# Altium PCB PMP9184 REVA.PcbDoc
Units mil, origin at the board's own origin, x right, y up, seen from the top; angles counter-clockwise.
Board outline 2750 x 2500 mil, 2 copper layers (Top Layer, Bottom Layer), stack 64.8 mil thick; 44 components, 18 nets, 116 pads, 55 vias.
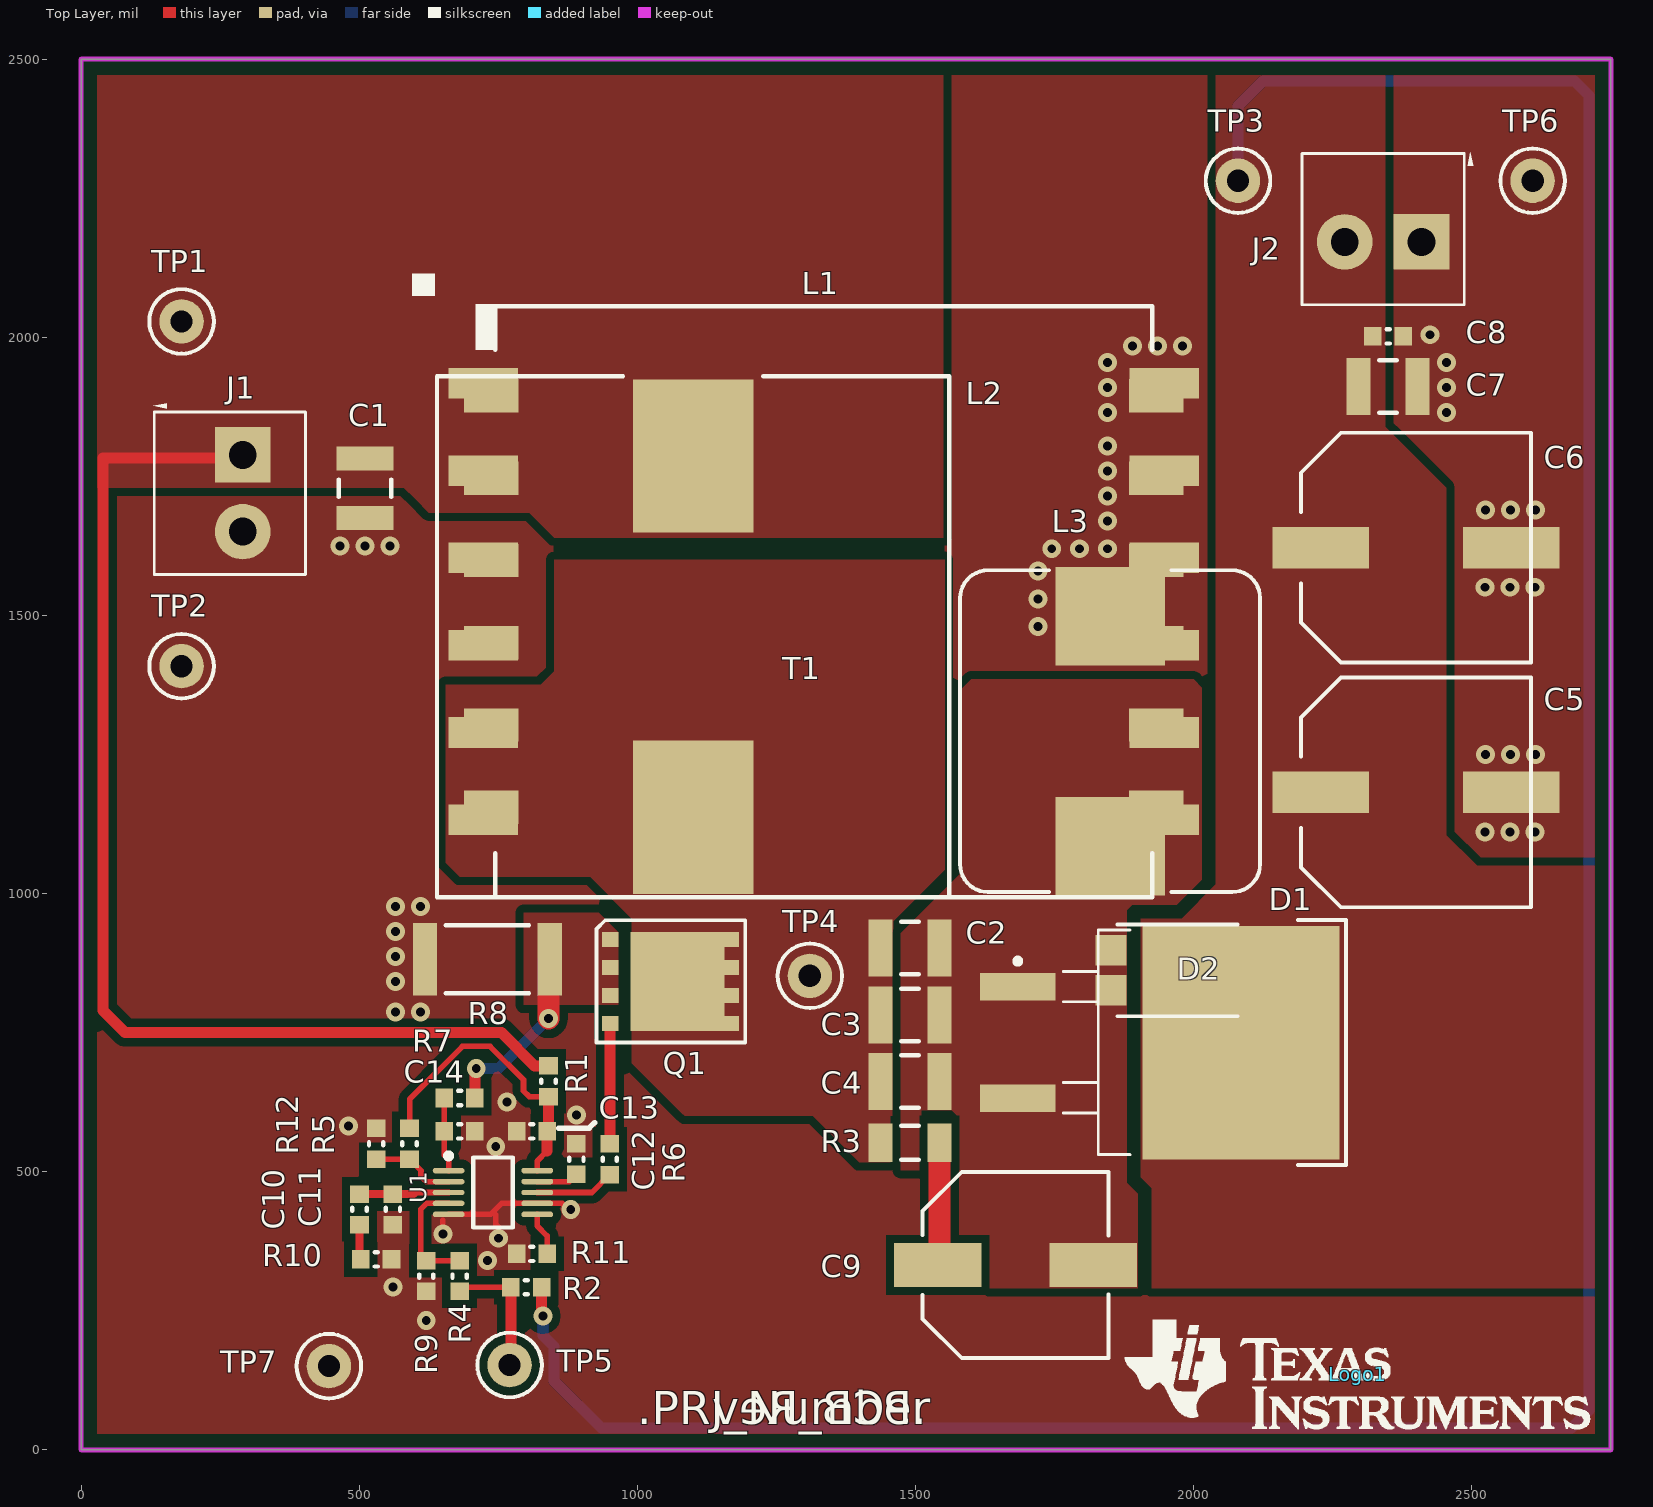
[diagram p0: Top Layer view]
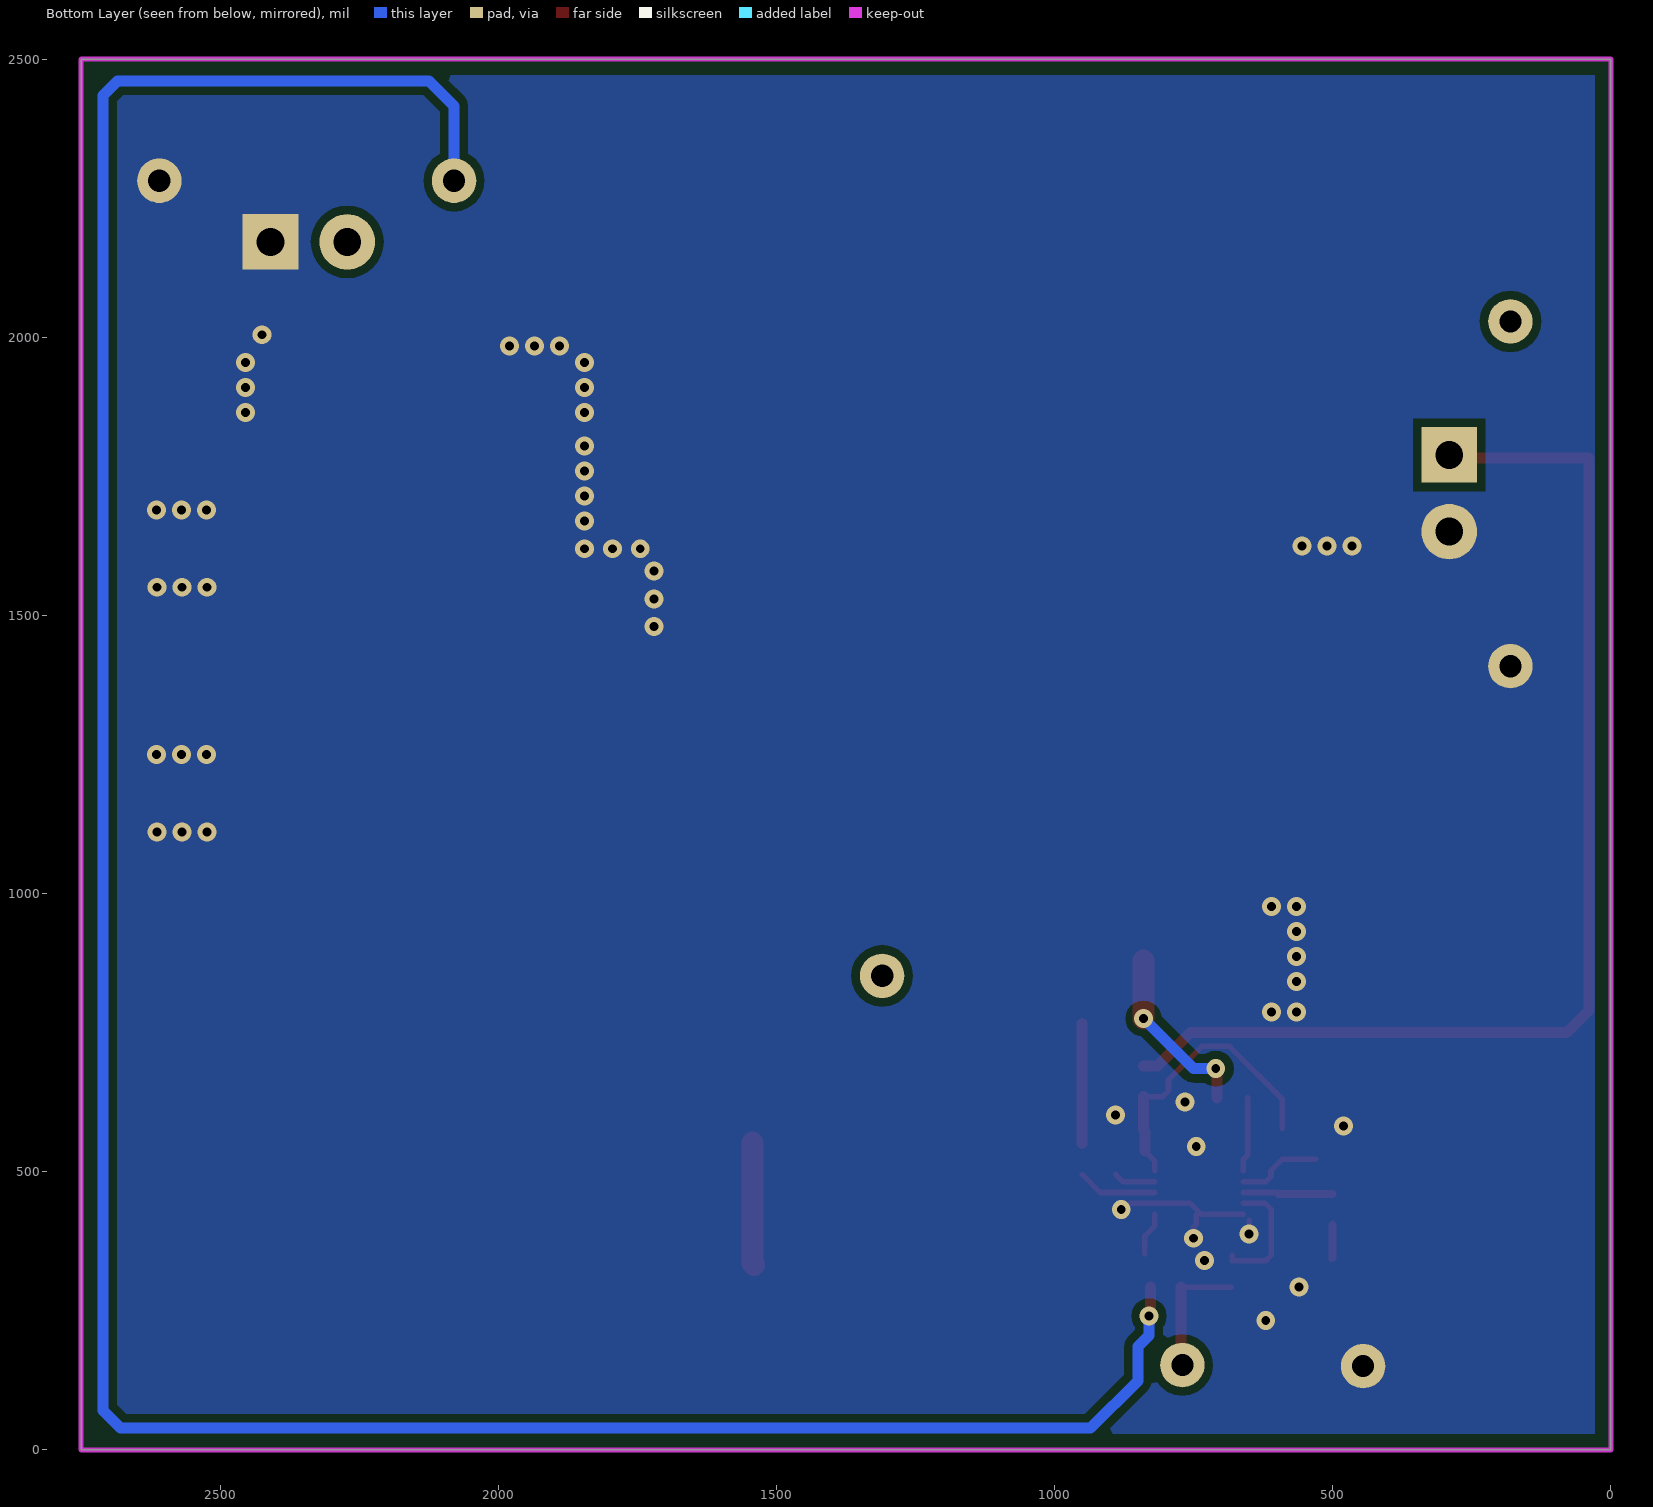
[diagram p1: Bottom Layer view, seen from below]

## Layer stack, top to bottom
Top Layer: signal copper 2.8
Dielectric: core 59.2, FR-4, Dk 4.8
Bottom Layer: signal copper 2.8

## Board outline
0,0 2750,0 2750,2500 0,2500

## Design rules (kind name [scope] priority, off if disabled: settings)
AcuteAngle [All] p1: minimum=4.50000000000000E+0001 checktracksonly=FALSE
AssemblyTestPointUsage [All] p1: valid=2
Clearance Clearance_BoardEdge_MountingHoles [OnCopper and InComponentClass('Mounting Holes') vs IsKeepOut] p1: gap=40
Clearance Clearance_BoardEdge_Poly [OnCopper and InPoly vs IsKeepOut] p2: gap=25
Clearance Clearance_BoardEdge [OnCopper and Not InComponentClass('Logo') and not InComponentClass('FiducialMark') and not InRegion(1000,500,4000,800) and Not IsKeepout vs IsKeepOut] p3: gap=15
Clearance Clearance_Poly [InPolygon] p4: gap=15
Clearance [All] p5: gap=8
ComponentClearance ComponentClearance_Logo [InComponentClass('Logo')] p1: gap=20 collisioncheckmode=3 verticalgap=10 showdistances=FALSE
ComponentClearance ComponentClearance_ScrewToNut [(HasFootprint('NY PMS 440 0025 PH')) vs (HasFootprint('Keystone_1902C'))] p2: gap=5 collisioncheckmode=3 verticalgap=10 showdistances=FALSE
ComponentClearance ComponentClearance_MountingHoles [InComponentClass('Mounting Holes')] p3: gap=250 collisioncheckmode=3 verticalgap=100000 showdistances=FALSE
ComponentClearance ComponentClearance_SmallPassives [HasFootprint('0201*') or HasFootprint('0402*') or HasFootprint('0508') or HasFootprint('0603*') or HasFootprint('0612') or HasFootprint('0805*') or HasFootprint('0815*') or HasFootprint('0830*') or HasFootprint('1206*') or HasFootprint('1210*') or HasFootprint('1808*') or HasFootprint('1812*') or HasFootprint('1825*') or HasFootprint('2010*') or HasFootprint('2220*') or HasFootprint('2225*') or HasFootprint('2512*') or HasFootprint('2728*') or HasFootprint('3518*') vs HasFootprint('0201*') or HasFootprint('0402*') or HasFootprint('0508') or HasFootprint('0603*') or HasFootprint('0612') or HasFootprint('0805*') or HasFootprint('0815*') or HasFootprint('0830*') or HasFootprint('1206*') or HasFootprint('1210*') or HasFootprint('1808*') or HasFootprint('1812*') or HasFootprint('1825*') or HasFootprint('2010*') or HasFootprint('2220*') or HasFootprint('2225*') or HasFootprint('2512*') or HasFootprint('2728*') or HasFootprint('3518*')] p4: gap=10 collisioncheckmode=3 verticalgap=10 showdistances=FALSE
ComponentClearance ComponentClearance_THtoSMT [IsThruComponent vs IsSMTComponent] p5: gap=15 collisioncheckmode=3 verticalgap=20 showdistances=FALSE
ComponentClearance ComponentClearance_THtoTH [IsThruComponent vs IsThruComponent] p6: gap=50 collisioncheckmode=3 verticalgap=30 showdistances=FALSE
ComponentClearance [All] p7: gap=25 collisioncheckmode=3 verticalgap=10 showdistances=FALSE
DiffPairsRouting [All] p1: maxlimit=100 minlimit=10 mostfreqgap=10 maxuncoupledlength=1000
FabricationTestPointUsage TestPointUsage [All] p1: valid=2 allowmultiple=FALSE
FabricationTestpoint Testpoint [All] p1: side=3 testpointundercomponent=TRUE minsize=40 maxsize=100 preferedsize=60 minholesize=0 maxholesize=40 preferedholesize=32 testpointgrid=1 allowsidetop=TRUE allowsidebottom=TRUE usegrid=TRUE gridtolerance=0.01
FanoutControl Fanout_LCC [IsLCC] p1: bgadir=Out bgaviamode=Centered fanoutstyle=Auto fanoutdirection=Alternating viagrid=1 // Fanout_LCC (Default Rule)
FanoutControl Fanout_BGA [IsBGA] p2: bgadir=Out bgaviamode=Centered fanoutstyle=Auto fanoutdirection=Alternating viagrid=1 // Fanout_BGA (Default Rule)
FanoutControl Fanout_Default [All] p4: bgadir=Out bgaviamode=Centered fanoutstyle=Auto fanoutdirection=Alternating viagrid=1 // Fanout_Default (Default Rule)
FanoutControl Fanout_Small [(CompPinCount < 5)] p5: bgadir=Out bgaviamode=Centered fanoutstyle=Auto fanoutdirection=OutThenIn viagrid=1 // Fanout_Small (Default Rule)
HoleSize [All] p1: absolutevalues=TRUE maxlimit=251 minlimit=8 maxpercent=80.000 minpercent=20.000
MinimumAnnularRing [All] p1: minimumring=9
MinimumSolderMaskSliver MinimumSolderMaskSliver_Logo [InComponentClass('Logo') vs InComponentClass('Logo')] p1: minsoldermaskwidth=0.7
MinimumSolderMaskSliver [All] p2: minsoldermaskwidth=4
PlaneConnect [All] p1: planeconnectstyle=Direct reliefexpansion=10 reliefentries=4 reliefconductorwidth=10 reliefairgap=10
PolygonConnect [All] p1: connectstyle=Direct reliefconductorwidth=10 reliefentries=4 polygonreliefangle="90 Angle" airgapwidth=10
RoutingVias [All] p1: holewidth=16 width=34 viastyle="Through Hole" minholewidth=8 minwidth=26 maxholewidth=40 maxwidth=65
SMDToCorner [All] p1: distance=30000
SilkToSilkClearance [All] p1: silktosilkclearance=0
SilkscreenOverComponentPads [All] p1: minsilkscreentomaskgap=0
SolderMaskExpansion [All] p1: expansion=3
Width [All] p1: maxlimit=100 minlimit=6 preferedwidth=10 checkconnectedcopper=TRUE
14 further rules are at their usual default settings.

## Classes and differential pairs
component class Logo: Logo1

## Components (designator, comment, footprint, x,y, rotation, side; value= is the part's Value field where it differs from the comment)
C1 "C3225X7R1E106M250AC" 1210L 510,1728.86 r90 top
C2 "C3225X7R1E106M250AC" 1210L 1490,901.93 r0 top
C3 "C3225X7R1E106M250AC" 1210L 1490.13,781.69 r0 top
C4 "C3225X7R1E106M250AC" 1210L 1490.13,661.69 r0 top
C5 "25SVPF180M" SM_RADIAL_10AMM 2400,1181.93 r0 top
C6 "25SVPF180M" SM_RADIAL_10AMM 2400,1621.93 r0 top
C7 "C3225X7R1E106M250AC" 1210L 2350,1911.93 r180 top
C8 "C1608X7R1H104K" 0603L 2350,2001.93 r0 top
C9 "EEE-FK1E151P" SM_RADIAL_F 1680,331.93 r0 top
C10 "C1608X5R1E474K" 0603L 500,431.93 r270 top
C11 "" 0603L 560,431.93 r270 top
C12 "C1608X7R1E105K" 0603L 890,522.24 r90 top
C13 "C1608X7R1E105K" 0603L 810,572.24 r180 top
C14 "C1608X7R1H102K" 0603L 680,572.24 r0 top
D1 "SBR10U40CTB" DDPAK 1930,731.93 r0 top
D2 "PDS1040L" PowerDI5 1930,861.93 r0 top
J1 "ED555/2DS" TERM_BLK_ED555-2DS 290,1788.86 r270 top
J2 "ED555/2DS" TERM_BLK_ED555-2DS 2410,2171.93 r180 top
L1 "RL-9426" IND_RENCO_1050_X_1300 1335,1525 r270 top
L2 "74435582200" IND_WE-HCI_2212 1100,1461.93 r90 top
L3 "7443551221" WE-HCA2 1850,1291.93 r90 top
Logo1 "Texas Instruments" TI_Stacked_Overlay_Small 2295,135 r0 top
Q1 "CSD18504Q5A" TRANS_NexFET_Q5A 1060,841.93 r0 top
R1 "CRCW060310R0JNEA" 0603L 840,662.24 r90 top
R2 "CRCW060349R9FKEA" 0603L 800,291.93 r0 top
R3 "CRCW12061R00FKEA" 1206L 1490,551.93 r0 top
R4 "CRCW060349K9FKEA" 0603L 680,311.93 r270 top
R5 "CRCW0603100KFKEA" 0603L 590,549.8 r90 top
R6 "CRCW06030000Z0EA" 0603L 950,521.93 r90 top
R7 "CRCW0603221RFKEA" 0603L 680,632.24 r180 top
R8 "CSNL2512FT5L00" 2512L 730,881.93 r0 top
R9 "CRCW06035K36FKEA" 0603L 620,311.93 r90 top
R10 "CRCW06031K00FKEA" 0603L 530,341.93 r180 top
R11 "CRCW0603140KFKEA" 0603L 810,351.93 r0 top
R12 "CRCW060333K2FKEA" 0603L 530,549.8 r270 top
T1 "750314332" WURTH_750314332 1335,1525 r0 top
TP1 "5000" Keystone5000 180,2028.86 r0 top
TP2 "5001" Keystone5001 180,1408.86 r0 top
TP3 "5000" Keystone5000 2080,2281.93 r0 top
TP4 "5000" Keystone5000 1310,851.93 r0 top
TP5 "5000" Keystone5000 770,151.93 r0 top
TP6 "5001" Keystone5001 2610,2281.93 r0 top
TP7 "5001" Keystone5001 445,150 r0 top
U1 "LM3481MM" MUB10A_L 740,462.24 r0 top

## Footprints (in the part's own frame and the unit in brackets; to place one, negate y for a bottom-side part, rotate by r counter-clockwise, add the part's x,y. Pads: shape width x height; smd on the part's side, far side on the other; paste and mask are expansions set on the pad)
0603L [mm] "0603 from SM-752 data"
  rect 0.8x0.85 smd: 1(-0.7,0) 2(0.7,0)
  silkscreen extent -0.07,-0.33 0.07,0.33, body extent -0.87,-0.47 0.87,0.47, height 0.85
1206L [mm] "1206 from SM-752 data"
  rect 1.1x1.75 smd: 1(-1.35,0) 2(1.35,0)
  silkscreen extent -0.4,-0.77 0.4,0.77, body extent -1.7,-0.9 1.7,0.9, height 1.35
1210L [mm] "1210 from SM-752 data"
  rect 1.1x2.6 smd: 1(-1.35,0) 2(1.35,0)
  silkscreen extent -0.4,-1.2 0.4,1.2, body extent -1.7,-1.35 1.7,1.35, height 1.35
2512L [mm] "Chip Resistor, Body 6.3x3.2mm, IPC High Density"
  rect 1.1x3.3 smd: 1(-2.85,0) 2(2.85,0)
  silkscreen extent -1.9,-1.55 1.9,1.55, body extent -3.22,-1.67 3.22,1.67, height 0.71
DDPAK [mil] "D2-PAK, 3-Pads, Body 9.7x10.4mm (max), TO-263AB, using Vishay Silionix recommended pad sizes"
  rect 135x49.49 smd: 1(-246.06,100) 3(-246.06,-100)
  rect 355x420 smd paste-181.1: 4(155.51,0)
  silkscreen extent -251,-220 344,220, body extent -295,-202 324,202, height 180
IND_RENCO_1050_X_1300 [mil]
  rect 55x125 smd: 1(-392.5,-612.5) 2(-235.5,-612.5) 3(-78.5,-612.5) 4(78.5,-612.5) 5(235.5,-612.5) 6(392.5,-612.5) 7(392.5,612.5) 8(235.5,612.5) 9(78.5,612.5) 10(-78.5,612.5) 11(-235.5,612.5) 12(-392.5,612.5)
  silkscreen extent -590,-740 -550,-700
IND_WE-HCI_2212 [mm] "WERTH ELEKTRONIK"
  rect 7x5.5 smd: 1(-8.25,0) 2(8.25,0)
  silkscreen extent -11.9,-11.7 11.9,11.7, body extent -11.75,-11.5 11.75,11.5, height 12.4
Keystone5000 [mil] "For Keystone 500x miniature loop terminals"
  round 80 hole 40: 1(0,0)
  silkscreen extent -58,-58 58,58, body extent -49,-49 49,49, height 182
Keystone5001 [mil] "For Keystone 500x miniature loop terminals"
  round 80 hole 40: 1(0,0)
  silkscreen extent -58,-58 58,58, body extent -49,-49 49,49, height 182
MUB10A_L [mm] "TSSOP, 10-Leads, Body 3x3mm, Pitch 0.5mm, IPC High Density"
  oval 1.45x0.25 smd: 1(-2.025,1) 2(-2.025,0.5) 3(-2.025,0) 4(-2.025,-0.5) 5(-2.025,-1) 6(2.025,-1) 7(2.025,-0.5) 8(2.025,0) 9(2.025,0.5) 10(2.025,1)
  silkscreen extent -2.15,-1.6 0.9,1.8, body extent -1.6,-1.6 1.6,1.6, height 1.09
PowerDI5 [mm] "Diodes Inc recommended land pattern, ap02001.pdf rev 60"
  rect 1.4x1.39 smd: 1(-1.991,0.92) 2(-1.991,-0.92)
  rect 4.86x3.36 smd: 3(1.991,0)
  silkscreen extent -1.7,-2.1 3.8,2.1, body extent -2.27,-2.03 4.33,2.03, height 1.17
SM_RADIAL_10AMM [mm] "10 x 7.9mm:  Sanyo Oscon F8"
  rect 4.4x1.9 smd: 1(-4.35,0) 2(4.35,0)
  silkscreen extent -5.25,-5.25 5.25,5.25, body extent -5.26,-5.26 5.26,5.26, height 8
SM_RADIAL_F [mm] "8 x 10.2mm:  Panasonic F"
  rect 4x2 smd: 1(-3.55,0) 2(3.55,0)
  silkscreen extent -4.25,-4.25 4.25,4.25, body extent -4.26,-4.26 4.26,4.26, height 10.5
TERM_BLK_ED555-2DS [mil]
  rect 100x100 hole 50: 1(0,0)
  round 100 hole 50: 2(138,0)
  silkscreen extent -93,-161 215,113, body extent -69,-150 207,106, height 323
TI_Stacked_Overlay_Small [mil]
  silkscreen extent -418,-98 418,98
TRANS_NexFET_Q5A [mm] "TI recommended land pattern (nominal) M0139-01"
  rect 0.75x0.675 smd paste-0.1 mask+0.051: 1(-2.776,1.917) 2(-2.776,0.639) 3(-2.776,-0.639) 4(-2.776,-1.917)
  rect 0.655x0.675 smd paste-0.1 mask+0.051: 5(2.776,-1.917) 6(2.776,-0.639) 7(2.776,0.639) 8(2.776,1.917)
  rect 4.295x4.51 smd paste-2.2 mask+0.051: 9(0.301,0)
  silkscreen extent -3.4,-2.8 3.4,2.8, body extent -3.05,-2.5 3.05,2.5, height 1.11
WE-HCA2 [mm] "Wurth Electronik recommended land pattern"
  rect 4.5x5 smd: 1(-5.25,0) 2(5.25,0)
  silkscreen extent -7.35,-6.85 7.35,6.85, body extent -7.01,-6.65 7.01,6.67, height 5
WURTH_750314332 [mm] "Wurth"
  rect 2.5x1.52 smd: 1(-15.19,9.4) 2(-15.19,5.64) 3(-15.19,1.88) 4(-15.19,-1.88) 5(-15.19,-5.64) 6(-15.19,-9.4) 7(15.19,-9.4) 8(15.19,-5.64) 9(15.19,-1.88) 10(15.19,1.88) 11(15.19,5.64) 12(15.19,9.4)
  silkscreen extent -15.9,-13.5 15,13.6, body extent -15,-13.51 15,13.51, height 13.98

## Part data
C1 C2 C3 C4 C7: library part C3225X7R1E106M, "CAP, CERM, 10uF, 25V, +/-20%, X7R, 1210"
C5 C6: library part 25SVP22M, "CAP, OS-CON, 180uF, 25V, +/-20%, 0.016 ohm, 10x10.3 SMD"
C8: "CAP, CERM, 0.1uF, 50V, +/-10%, X7R, 0603"
C9: "CAP, AL, 150uF, 25V, +/-20%, 0.16 ohm, SMD"
C10: library part C1608X5R1A474K, "CAP, CERM, 0.33uF, 25V, +/-10%, X5R, 0603"
C11: library part C1608X5R1A474K, "CAP, CERM, OPEN"
C12 C13: library part C1608X7R1C105K, "CAP, CERM, 1uF, 25V, +/-10%, X7R, 0603"
C14: "CAP, CERM, 1000pF, 50V, +/-10%, X7R, 0603"
D1: "Diode, Super Barrier Rectifier, 40V, 5A, DDPAK"
D2: library part PDS1040L-13, "Diode, Schottky, 40V, 10A, PowerDI5"
J1 J2: "Terminal Block, 6A, 3.5mm Pitch, 2-Pos, TH"
L1: library part IND_RL-9426, "Inductor, Coupled, ±10%"
L2: library part 74435581000, "Inductor, Drum Core, Ferrite, 22uH, 15A, 0.0070 ohm, SMD"
L3: library part 7443551181, "Inductor, Shielded Drum Core, WE-Perm, 22uH, 6A, 0.0247 ohm, SMD"
Logo1: library part TI_Logo, "Texas Instrument Corporate Signature"
Q1: "MOSFET, N-CH, 40V, 15A, SON 5x6mm"
R1: "RES, 10 ohm, 1%, 0.1W, 0603"
R2: "RES, 49.9 ohm, 1%, 0.1W, 0603"
R3: "RES, 1.00 ohm, 1%, 0.25W, 1206"
R4: "RES, 49.9k ohm, 1%, 0.1W, 0603"
R5: "RES, 100k ohm, 1%, 0.1W, 0603"
R6: "RES, 0 ohm, 5%, 0.1W, 0603"
R7: "RES, 221 ohm, 1%, 0.1W, 0603"
R8: "RES, 0.005 ohm, 1%, 2W, 2512"
R9: "RES, 5.36k ohm, 1%, 0.1W, 0603"
R10: "RES, 1.00k ohm, 1%, 0.1W, 0603"
R11: "RES, 140k ohm, 1%, 0.1W, 0603"
R12: "RES, 33.2k ohm, 1%, 0.1W, 0603"
T1: "Transformer, 16uH, SMT"
TP1 TP3 TP4 TP5: "Test Point, TH, Miniature, Red"
TP2 TP6 TP7: "Test Point, TH, Miniature, Black"
U1: "High Efficiency Low-Side N-Channel Controller for Switching Regulators, 10-pin MSOP"

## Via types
v1: diameter 34, hole 16, Top Layer to Bottom Layer, 55 vias

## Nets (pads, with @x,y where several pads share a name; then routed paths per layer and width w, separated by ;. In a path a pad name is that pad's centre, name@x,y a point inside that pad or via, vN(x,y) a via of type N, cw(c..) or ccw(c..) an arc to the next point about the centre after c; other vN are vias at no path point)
GND: C1.1 C5.2 C6.2 C7.1 C8.2 C11.2 C12.2 C13.2 C14.2 J1.2 J2.1 L1.11 L1.12 L3.2 R8.1 R9.1 R10.1 R11.1 R12.1 T1.11 T1.12 TP2.1 TP6.1 TP7.1 U1.5 U1.7 | length 302.3
  Top Layer w10: v1(650,387.93) 650,412.6 ; U1.5 735.94,422.87 ; v1(750,380) 750,400 745,405 745,421.93 740,426.93 755.63,442.56 U1.7 864.52,442.56 875.15,431.93 v1(880,431.93)
  other v1: 620,231.93 560,291.93 730,340 745,545 480,581.93 890,601.93 765,625 565,786.93 610,786.93 565,841.93 565,886.93 565,931.93 565,976.93 610,976.93 2524.32,1110.84 2569.32,1110.84 2614.32,1110.84 2525,1250 2570,1250 2615,1250 1720,1480 1720,1530 2524.32,1550.84 2569.32,1550.84 2614.32,1550.84 1720,1580 1745,1620 1795,1620 1845,1620 465,1625 510,1625 555,1625 1845,1670 2525,1690 2570,1690 2615,1690 1845,1715 1845,1760 1845,1805 1845,1865 2455,1865 1845,1910 2455,1910 1845,1955 2455,1955 1890,1985 1935,1985 1980,1985 2425,2005
NetC1_2: C1.2 J1.1 L1.1 L1.2 L2.2 R1.2 T1.1 T1.2 TP1.1 | length 2090.2
  Top Layer w20: J1.1 284.64,1783.5 38.5,1783.5 38.5,790 78.5,750 755,750 815.2,689.8 R1.2
NetC2_1: C2.1 C3.1 C4.1 L1.5 L1.6 L2.1 Q1.5 Q1.6 Q1.7 Q1.8 Q1.9 R3.1 T1.5 T1.6 TP4.1
NetC2_2: C2.2 C3.2 C4.2 C9.2 D1.1 D1.3 D2.1 D2.2 L1.7 L1.8 L3.1 T1.7 T1.8
NetC9_1: C9.1 R3.2 | length 221.2
  Top Layer w40: C9.1 1543.15,334.84 R3.2
NetC10_1: C10.1 C11.1 U1.3 | length 161.4
  Top Layer w10: 597.56,459.49 600.31,462.24 U1.3
  Top Layer w15: C10.1 C11.1 597.56,459.49
NetC10_2: C10.2 R10.2 | length 63.5
  Top Layer w10: R10.2@500,344.37 R10.2
  Top Layer w15: R10.2@500,344.37 C10.2
NetC12_1: C12.1 U1.9 | length 75.6
  Top Layer w10: U1.9 877.24,481.93 C12.1
NetC13_1: C13.1 R1.1 R5.2 U1.10 | length 532.6
  Top Layer w10: R5.2 590,630 685,725 735,725 795,665 795,645 805.32,634.68 R1.1 ; U1.10 819.72,518.9 837.56,536.73
  Top Layer w20: 837.56,536.73 C13.1 840,574.68 R1.1
NetC14_1: C14.1 R7.2 U1.1 | length 133.9
  Top Layer w10: R7.2 C14.1 652.44,529.49 660.28,521.65 U1.1
NetQ1_1: Q1.1 Q1.2 Q1.3 R7.1 R8.2 | length 325.8
  Top Layer w20: R7.1 707.56,682.56 v1(710,685)
  Top Layer w40: v1(840,775) R8.2@840,879.72
  Bottom Layer w20: v1(710,685) 750,685 v1(840,775)
NetQ1_4: Q1.4 R6.2 | length 216.3
  Top Layer w20: R6.2@950.7,550.18 Q1.4
NetR2_1: R2.1 R4.2 TP5.1 | length 227.6
  Top Layer w10: R4.2@682.44,291.93 R2.1
  Top Layer w20: TP5.1@772.44,154.37 R2.1
NetR4_1: R4.1 R9.2 U1.4 | length 221.3
  Top Layer w10: U1.4 620.63,442.56 610,431.93 610,349.49 R9.2 R4.1 R4.1@680,349.49
NetR5_1: R5.1 R12.2 U1.2 | length 153
  Top Layer w10: R12.2 R5.1 610.67,501.57 610.67,491.26 620,481.93 U1.2
NetR6_1: R6.1 U1.8 | length 143.6
  Top Layer w10: U1.8 917.87,462.24 R6.1
NetR11_2: R11.2 U1.6 | length 78.3
  Top Layer w10: U1.6 819.72,402.2 837.56,384.37 R11.2
VOUT: C5.1 C6.1 C7.2 C8.1 D1.4 D2.3 J2.2 R2.2 TP3.1 | length 5248.2
  Top Layer w20: R2.2 827.56,242.44 v1(830,240)
  Bottom Layer w20: v1(830,240) 830,205 850,185 850,123.5 935,38.5 2680,38.5 2711.5,70 2711.5,2435 2685,2461.5 2125,2461.5 2080,2416.5 TP3.1
pads on no net: L1.3 L1.4 L1.9 L1.10 T1.3 T1.4 T1.9 T1.10

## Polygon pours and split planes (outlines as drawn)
NetQ1_1 on Top Layer "Top Layer-No Net 4" (solid, pour order 5): 965,930 965,800 795,800 795,965 930,965
NetC2_1 on Top Layer "Top Layer-No Net 3" (solid, pour order 4): 1350,1600 1552.76,1600 1552.76,1045 1550,1045 1520,1015 1504.33,999.33 1445,999.33 1375.67,999.33 1350,1025
NetC2_1 on Top Layer "Top Layer-No Net 2" (solid, pour order 3): 655,1270 655,1375 913.81,1375 1460,828.81 1455,823.81 1455,516.5 1398.5,516.5 1385,530 1090,825 1090,935 1090,1115 985,1220 655,1220
NetC2_1 on Top Layer "Top Layer-No Net 1" (solid, pour order 2): 990,750 990,700 990,695 1080,605 1085,600 1460,600 1460,1595 1455,1600 850,1600 850,1400 775,1325 655,1325 655,1055 680,1030 870,1030 915,1030 990,955
NetC1_2 on Top Layer "Top Layer-No Net" (solid, pour order 1): 0,2500 0,1730 580,1730 600,1710 625,1685 780,1685 805,1685 850,1640 1550,1640 1550,2500
NetC2_2 on Top Layer "Top Layer-No Net 5" (solid, pour order 6): 1520,955.08 1500.08,955.08 1500,955 1500,610 1585,610 1600,595 1600,415 1645,415 1665,395 1680,380 1680,290 1900,290 1900,450 1900,460 1880,480 1880,620 1880,755 1880,941.65 1880,965 1880,970 1890,980 1945,980 1970,980 2015,1025 2015,1140 2015,1370 2000,1385 1600,1385 1580,1365 1580,1012.91 1570,1002.91
VOUT on Top Layer "Top Layer-No Net 6" (solid, pour order 7): 1905,515.39 1905,955 1978.66,955 2040,1016.34 2040,2500 2345,2500 2345,2270 2345,1839.31 2359.68,1824.63 2455,1729.31 2455,1695 2455,1105 2505,1055 2510,1050 2750,1050 2750,290 1925,290 1925,470 1905,490
GND on Top Layer "Top Layer-No Net 7" (solid, pour order 25): 0,2500 2747.5,2500 2750,2502.5 2750,0 2.5,0 0,-2.5
NetC2_2 on Top Layer "Top Layer-No Net 8" (solid, pour order 0): 1740,290 1633.98,290 1633.98,386.3 1578.45,386.3 1578.45,597 1568.87,606.57 1565.45,610 1510,610 1510,504.63 1507.85,502.48 1473.5,502.48 1473.5,928.5 1585,1040 1715,910 1740,910
NetC2_1 on Top Layer "Top Layer-No Net 9" (solid, pour order 29): 1552.76,1070 1552.76,1042.76 1520,1010 1445,935 1410,935 1410,1070
GND on Bottom Layer "Bottom Layer-No Net" (solid, pour order 24): 0,2502.5 2.5,2500 2750,2500 2750,-2.5 2747.5,0 0,0

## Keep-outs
Keep-Out Layer:
  lines w5: -2.5,0 ccw(c0,0) 0,-2.5 ; -2.5,0 ccw(c0,0) 0,-2.5 ; -2.5,0 -2.5,2500 ; -2.5,2500 cw(c0,2500) 0,2502.5 ; -2.5,2500 cw(c0,2500) 0,2502.5 ; 0,-2.5 2750,-2.5 ; 0,2502.5 2750,2502.5 ; 2750,-2.5 ccw(c2750,0) 2752.5,0 ; 2750,-2.5 ccw(c2750,0) 2752.5,0 ; 2750,2502.5 cw(c2750,2500) 2752.5,2500 ; 2750,2502.5 cw(c2750,2500) 2752.5,2500 ; 2752.5,0 2752.5,2500
  lines w7: 0,0 0,2500 2750,2500 2750,0 0,0
  text ".Layer_Name" at 577,-858.49 h60

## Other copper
Top Layer:
  text ".Layer_Name" at 577,-858.49 h60
Bottom Layer:
  text ".Layer_Name" at 577,-858.49 h60

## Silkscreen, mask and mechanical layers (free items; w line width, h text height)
Top Overlay:
  lines w10: 858,578 913,578 923,588
  text ".PRJ_Number" at 1000,45 h60
  text ".PCB_Rev" at 1520,45 h60
  text ".Layer_Name" at 577,-858.49 h60
Bottom Overlay:
  text ".Layer_Name" at 577,-858.49 h60
Top Paste:
  text ".Layer_Name" at 577,-858.49 h60
Bottom Paste:
  text ".Layer_Name" at 577,-858.49 h60
Top Solder:
  text ".Layer_Name" at 577,-858.49 h60
  text ".Layer_Name" at 577,-858.49 h60
Bottom Solder:
  text ".Layer_Name" at 577,-858.49 h60
Drill Guide:
  text ".Layer_Name" at 577,-858.49 h60
M1 Board Outline:
  the board outline again, w7
  text ".Layer_Name" at 577,-858.49 h60
M2 Board Dimensions:
  rectangle: -0.5,-285.5 124.5,-160.5
  rectangle: 124.5,-410.5 499.5,-285.5
  lines w7: -0.5,-285.5 999.5,-285.5 ; 124.5,-410.5 124.5,-160.5 ; 249.5,-410.5 249.5,-160.5 ; 499.5,-410.5 499.5,-160.5 ; 749.5,-410.5 749.5,-160.5 ; -0.5,-410.5 999.5,-410.5 999.5,-160.5 -0.5,-160.5 -0.5,-410.5
  lines w10: -0.5,-475.5 -0.5,-455.5 ; 59.5,-485.5 -0.5,-465.5 ; 59.5,-445.5 -0.5,-465.5 ; 223.58,-465.5 -0.5,-465.5 ; 775.42,-465.5 999.5,-465.5 ; 939.5,-485.5 999.5,-465.5 ; 939.5,-445.5 999.5,-465.5 ; 999.5,-475.5 999.5,-455.5
  text "1000 (mil)" at 233.58,-501.49 h60
  text ".Layer_Name" at 577,-858.49 h60
M3 3D STEP Top:
  text ".Layer_Name" at 577,-858.49 h60
M4 3D STEP Bottom:
  text ".Layer_Name" at 577,-858.49 h60
M5 Assembly Top:
  lines w7: 5139,110.5 6264,110.5 ; 5139,233 6261.5,233 ; 5454,-9.5 5454,353 ; 5839,-9.5 5139,-9.5 ; 5839,353 5139,353 ; 5139,-9.5 6264,-9.5 6264,353 5139,353 ; 5139,-9.5 5139,353
  lines w10: -292,-930.17 6308,-930.17 ; -292,-726.83 6310,-726.83 ; -292,-523.5 -292,-1133.5 3713,-1133.5 6310,-1133.5 6310,-523.5 -291.5,-523.5 -291.5,-1133.5 1284,-1133.5 ; 2173,-1133.5 2173,-523.5 ; 3440,-726.83 3440,-523.5 ; 4280,-726.83 4280,-523.5 ; 4902,-1140 4902,-937.17
  text "TABLE 1" at 5526.5,388 h40
  text "Variant" at 5164,278 h40
  text "Label text" at 5599,278 h40
  text "001" at 5231.5,158 h40
  text "ChangeMe!" at 5509,155.5 h40
  text "002" at 5231.5,33 h40
  text "ChangeMe!" at 5504,30.5 h40
  text "PCB VIEWED FROM TOP SIDE" at -228.5,-655.67 h60
  text "BOARD #:" at 2248,-655.67 h60
  text ".PRJ_Number" at 2793.5,-655.67 h60
  text "REV:" at 3638,-655.67 h60
  text ".PCB_Rev" at 3929.5,-655.67 h60
  text "SVN REV:" at 4476,-655.67 h60
  text ".VersionControl_RevNumber" at 4982,-655.67 h60
  text "IGNORE ->" at -228.5,-858.49 h60
  text "PLOT NAME =" at -228.5,-1064.34 h60
  text ".plot_File_Name" at 577,-1064.34 h60
  text "GENERATED    :" at 2250,-1064.34 h60
  text ".Print_Date" at 3119.5,-1064.34 h60
  text ".Print_Time" at 3848.5,-1064.34 h60
  text "TEXAS INSTRUMENTS" at 5113,-1064.34 h60
M6 Assembly Bottom:
  lines w10: -292.5,-727.33 6309.5,-727.33 ; -290.5,-930.67 6309.5,-930.67 ; 1115.5,-1140.5 1115.5,-937.67 ; 1737.5,-727.33 1737.5,-524 ; 2577.5,-727.33 2577.5,-524 ; 3844.5,-1134 3844.5,-524 ; 4733.5,-1134 6309,-1134 6309,-524 -292.5,-524 -292.5,-1134 2304.5,-1134 6309.5,-1134 6309.5,-524
  text ".VersionControl_RevNumber" at 1035.5,-656.17 h60
  text "SVN REV:" at 1541.5,-656.17 h60
  text ".PCB_Rev" at 2088,-656.17 h60
  text "REV:" at 2379.5,-656.17 h60
  text ".PRJ_Number" at 3224,-656.17 h60
  text "BOARD #:" at 3769.5,-656.17 h60
  text "PCB VIEWED FROM BOTTOM SIDE" at 6246,-656.17 h60
  text "IGNORE ->" at 2547.85,-858.49 h60
  text "TEXAS INSTRUMENTS" at 904.5,-1064.84 h60
  text ".Print_Time" at 2169,-1064.84 h60
  text ".Print_Date" at 2898,-1064.84 h60
  text "GENERATED    :" at 3767.5,-1064.84 h60
  text ".plot_File_Name" at 5440.5,-1064.84 h60
  text "PLOT NAME =" at 6246,-1064.84 h60
M9 Title Sheet:
  drawing of 57 lines, arcs and shapes, not listed
  text "1" at 739.84,8036.5 h70
  text "2" at 3235.5,8036.5 h70
  text "3" at 5724.84,8036.5 h70
  text "4" at 8231.51,8036.5 h70
  text "5" at 10730.5,8036.5 h70
  text "6" at 13235.5,8036.5 h70
  text "A" at -416.5,6893.5 h70
  text "A" at 14383.5,6893.5 h70
  text "B" at -416.5,4513.5 h70
  text "B" at 14383.5,4513.5 h70
  text "C" at -416.5,2138.5 h70
  text "C" at 14383.5,2138.5 h70
  text "PROJECT TITLE:" at 11343.5,277.5 h45
  text ".PRJ_Title" at 11393.5,144.17 h70
  text "DESIGNED FOR:" at 11343.5,-23.5 h45
  text ".PRJ_Customer" at 11393.5,-163.5 h70
  text "D" at -416.5,-231.5 h70
  text "D" at 14383.5,-231.5 h70
  text "FILE NAME:" at 11343.5,-323.5 h45
  text ".PCB_File_Name_No_Path" at 11393.5,-443.5 h70
  text "Texas Instruments (TI) and/or its licensors do not warrant the accuracy or completeness of this specification" at 6374,-605.34 h45
  text "ENGINEER:" at 11343.5,-613.5 h45
  text "LAYOUT BY:" at 12848.5,-613.5 h45
  text "or any information contained therein. TI and/or its licensors do not warrant that this design will meet" at 6329.01,-718 h45
  text ".PRJ_Engineer" at 11393.5,-768.49 h70
  text ".PCB_Layout" at 12899,-768.49 h70
  text "the specifications, will be suitable for your application or fit for any particular purpose, or will operate in" at 6329.01,-830.67 h45
  text ".Layer_Name" at 577,-858.49 h60
  text "ALTIUM DESIGNER VERSION:" at 12848.5,-923.5 h45
  text "an implementation. TI and/or its licensors do not warrant that the design is production worthy. You should" at 6329.01,-943.33 h45
  text "completely validate and test your design implementation to confirm the system functionality for your application." at 6374,-1056 h45
  text ".print_Scale" at 11393.5,-1056.83 h70
  text ".Application_BuildNumber" at 12899,-1056.83 h70
  text "1" at 739.84,-1263.5 h70
  text "2" at 3235.5,-1263.5 h70
  text "3" at 5724.84,-1263.5 h70
  text "4" at 8231.51,-1263.5 h70
  text "5" at 10730.5,-1263.5 h70
  text "6" at 13235.5,-1263.5 h70
M10 Fab Notes:
  drawing of 212 lines, arcs and shapes, not listed
  text "DESIGN INFORMATION" at 12381.02,6810 h60
  text "(REFER ALSO ARRAY/PANEL PROFILING INFORMATION)" at 12019.46,6648.29 h60
  text "BOARD SIZE" at 11333.46,6644 h60
  text "2500MIL" at 11795.78,6516.18 h60
  text "X" at 12301.46,6516.18 h60
  text "2750MIL" at 12532.78,6516.18 h60
  text "Number of Layers :" at 11736.46,6319 h60
  text "2" at 12831.27,6309 h60
  text "MIN. TRACK WIDTH:" at 11736.46,6180 h60
  text "8" at 12832.7,6180 h60
  text "MIL" at 12987.46,6180 h60
  text "MIN. CLEARANCE:" at 11736.46,6048 h60
  text "8" at 12832.7,6048 h60
  text "MIL" at 12987.46,6048 h60
  text "MIN. VIA PAD SIZE:" at 11736.46,5916 h60
  text "24" at 12802.71,5916 h60
  text "MIL" at 12987.46,5916 h60
  text "0.05mm (2MIL)" at 12431.46,5774.29 h60
  text "MINIMUM ANNULAR RING" at 11407.23,5770 h60
  text "EXTERNAL" at 13139.46,5770 h60
  text "PER" at 11607.23,5652 h60
  text "IPC-D-275 CLASS 2 LEVEL C" at 11827.23,5652 h60
  text "MIL, HOLES" at 13315.46,5539.71 h60
  text "+/-" at 12923,5539 h60
  text "+/-" at 13777,5539 h60
  text "REGISTRATION TOLERANCES:" at 11407.23,5534 h60
  text "METAL" at 12607,5534 h60
  text "5" at 13183.2,5534 h60
  text "3" at 14016.2,5534 h60
  text "MIL" at 14132.46,5534 h60
  text "MATERIAL:" at 11332.46,5324.54 h60
  text "FR-4 High Tg" at 12318.9,5184.21 h60
  text "FR-408" at 11753.46,5175.64 h60
  text "X" at 12165.46,5175.64 h60
  text "OTHER" at 13241.46,5175.64 h60
  text "62 MIL (1.6mm) +/-10%" at 12073.56,5012.92 h60
  text "THICKNESS:" at 11407.23,5008.64 h60
  text "X" at 11945.4,5008.64 h60
  text "OTHER" at 13358.46,5008.64 h60
  text "TOLERANCE:" at 11407.23,4850.64 h60
  text "X" at 12246.53,4850.64 h60
  text "ANSI IPC-6012 TYPE 3 CLASS 2" at 12433.48,4850.64 h60
  text "OTHER +/-" at 12433.46,4694.64 h60
  text "BOW & TWIST:" at 11407.23,4537.64 h60
  text "X" at 12246.53,4537.64 h60
  text "ANSI IPC-6012 TYPE 3 CLASS 2" at 12433.48,4537.64 h60
  text "OTHER +/-" at 12433.46,4379.13 h60
  text "COPPER THICKNESS (FINISHED):" at 11332.46,4243.64 h60
  text "X" at 13575,4095 h60
  text "1.4MIL (1oz)" at 12212.46,4090.92 h60
  text "2MIL (1.4oz)" at 12979.46,4090.92 h60
  text "2.8MIL (2oz)" at 13706.46,4090.92 h60
  text "OUTER:" at 11689.46,4086.64 h60
  text "X" at 12095,3945 h60
  text "1.4MIL (1oz)" at 12212.46,3933.92 h60
  text "2.8MIL (2oz)" at 12979.46,3933.92 h60
  text "N/A" at 13706,3934.29 h60
  text "INNER SIGNAL:" at 11400.38,3929.64 h60
  text "DRILLING:" at 11332.46,3790.64 h60
  text "REFERENCE:" at 11407.23,3673.64 h60
  text "X" at 12055.46,3673.64 h60
  text "AS SHOWN" at 12242.46,3673.64 h60
  text "X" at 12956.46,3673.64 h60
  text "NC_DRILL FILES" at 13093.46,3673.64 h60
  text "PTH MIN COPPER THICKNESS:" at 11407.23,3515.64 h60
  text "X" at 12757.46,3515.64 h60
  text "1MIL" at 12894.46,3515.64 h60
  text "OTHER" at 13391.46,3515.64 h60
  text "BOARD FINISH:" at 11332.46,3356.64 h60
  text "SILKSCREEN:" at 11487.68,3238.64 h60
  text "X" at 12436.46,3238.64 h60
  text "TOP" at 12562.46,3238.64 h60
  text "X" at 12946.46,3238.64 h60
  text "BOTTOM" at 13073.46,3238.64 h60
  text "SILKSCREEN COLOR:" at 11487.68,3071.64 h60
  text "X" at 12435.42,3071.64 h60
  text "WHITE" at 12562.46,3071.64 h60
  text "OTHER" at 13073.46,3071.64 h60
  text "SOLDER RESIST COLOR:" at 11487.68,2901.64 h60
  text "X" at 12655,2750 h60
  text "GREEN" at 12182.46,2742.44 h60
  text "BLUE" at 12773.46,2742.44 h60
  text "OTHER" at 13311.46,2742.44 h60
  text "IMMERSION GOLD (ENIG)" at 12393.46,2553.92 h60
  text "ENEPIG" at 13731,2550.64 h60
  text "SURFACE FINISH:" at 11332.46,2549.64 h60
  text "X" at 11500,2395 h60
  text "IMM. TIN/SILVER OR EQUIV" at 11662,2392.64 h60
  text "OTHER" at 13093.46,2392.64 h60
  text "ARRAY/PANEL:" at 11332.46,2213.64 h60
  text "CUT AND TRIM PER MECH LAYER 1" at 12393.46,2209.35 h60
  text "N.C. ROUTE" at 12393.46,2057.64 h60
  text "X" at 13072.46,2057.64 h60
  text "V. SCORE" at 13259.46,2057.64 h60
  text "CERTIFICATION:" at 11332.46,1920.64 h60
  text "MATERIALS AND WORKMANSHIP FOR ALL PCBS" at 12057.46,1920.64 h60
  text "TO MEET OR EXCEED THE REQUIREMENTS OF:" at 12057.46,1822.64 h60
  text "X" at 11683.96,1686.13 h60
  text "ANSI IPC-A-600F CLASS ->" at 11822.96,1686.13 h60
  text "X" at 13462.02,1686.13 h60
  text "2" at 13580.96,1686.14 h60
  text "1" at 13265.96,1684.64 h60
  text "3" at 13934.96,1684.64 h60
  text "X" at 11686.02,1526.64 h60
  text "UL 94V-0" at 11822.96,1526.64 h60
  text "X" at 12498.02,1526.64 h60
  text "RoHS" at 12634.96,1526.64 h60
  text "OTHER" at 13279.36,1526.64 h60
  text "PER ORDER" at 13676.42,1526.64 h60
  text "ADDITIONAL REQUIREMENTS:" at 11332.46,1385.64 h60
  text "MICROSECTION:" at 11407.23,1270.64 h60
  text "YES" at 12312.96,1270.64 h60
  text "REQUIRED" at 13174.46,1114.49 h60
  text "BARE BOARD ELEC. TEST:" at 11407.23,1111.64 h60
  text "NONE" at 12712.96,1111.64 h60
  text "X" at 13047.46,1111.64 h60
  text "PER ORDER" at 13766.46,1111.64 h60
  text "MANUFACTURER'S UL:" at 11407.23,954.64 h60
  text "RAIL" at 12572.96,950.35 h60
  text "METAL" at 13064.77,950.35 h60
  text "X" at 13440,950 h60
  text "SILK" at 13576.46,950.35 h60
  text ".Layer_Name" at 577,-858.49 h60
M11 Gerber Information:
  lines w10: -292,-930.17 6308,-930.17 ; -292,-726.83 6310,-726.83 ; -292,-523.5 -292,-1133.5 3713,-1133.5 6310,-1133.5 6310,-523.5 -291.5,-523.5 -291.5,-1133.5 1284,-1133.5 ; 2173,-1133.5 2173,-523.5 ; 3440,-726.83 3440,-523.5 ; 4280,-726.83 4280,-523.5 ; 4902,-1140 4902,-937.17
  text "ALL ARTWORK VIEWED FROM TOP SIDE" at -228.5,-655.67 h60
  text "BOARD #:" at 2248,-655.67 h60
  text ".PRJ_Number" at 2793.5,-655.67 h60
  text "REV:" at 3638,-655.67 h60
  text ".PCB_Rev" at 3929.5,-655.67 h60
  text "SVN REV:" at 4476,-655.67 h60
  text ".VersionControl_RevNumber" at 4982,-655.67 h60
  text "LAYER NAME =" at -228.5,-858.49 h60
  text "PLOT NAME =" at -228.5,-1064.34 h60
  text ".plot_File_Name" at 577,-1064.34 h60
  text "GENERATED    :" at 2250,-1064.34 h60
  text ".Print_Date" at 3119.5,-1064.34 h60
  text ".Print_Time" at 3848.5,-1064.34 h60
  text "TEXAS INSTRUMENTS" at 5113,-1064.34 h60
M12 Stackup:
  lines w7: 11360,7608.5 14225,7608.5 ; 11360,7742.6 14225,7742.6 ; 11300,6988 ccw(c11343,6988) 11343,6945 14242,6945 ccw(c14242,6988) 14285,6988 14285,7892 ccw(c14242,7892) 14242,7935 11343,7935 ccw(c11343,7892) 11300,7892 11300,6988
  text "Layer Stack Up Detail for: PMP9184 REVA.PcbDoc" at 11360,7793.5 h61
  text "Layer" at 11360,7692.6 h31
  text "Gerber" at 12371.76,7692.6 h31
  text "Copper" at 12970.93,7692.6 h31
  text "Dielectric" at 13620.71,7692.6 h31
  text "Name" at 11360,7630.6 h31
  text "Document" at 12371.76,7630.6 h31
  text "Thickness" at 12970.93,7630.6 h31
  text "Material" at 13620.71,7630.6 h31
  text "Top Solder Mask" at 11360,7512.19 h43
  text "(.GTS)" at 12371.76,7512.19 h43
  text "Solder Resist" at 13620.71,7512.19 h43
  text "Top Layer" at 11360,7388.44 h43
  text "(.GTL)" at 12371.76,7388.44 h43
  text "2.8mil" at 12970.93,7388.44 h43
  text "FR-4" at 13620.71,7326.56 h43
  text "Bottom Layer" at 11360,7264.69 h43
  text "(.GBL)" at 12371.76,7264.69 h43
  text "2.8mil" at 12970.93,7264.69 h43
  text "Bottom Solder Mask" at 11360,7140.94 h43
  text "(.GBS)" at 12371.76,7140.94 h43
  text "Solder Resist" at 13620.71,7140.94 h43
  text ".Layer_Name" at 577,-858.49 h60
M13 Component Bodies Top:
  text ".Layer_Name" at 577,-858.49 h60
M14 Component Bodies Bottom:
  text ".Layer_Name" at 577,-858.49 h60
M15 Courtyards Top:
  text ".Layer_Name" at 577,-858.49 h60
M16 Courtyards Bottom:
  text ".Layer_Name" at 577,-858.49 h60
Drill Drawing:
  text ".legend" at 5122.5,725.5 h60
  text "Drill Table" at 5147.5,540.5 h60
  text ".Layer_Name" at 577,-858.49 h60

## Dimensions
0,0 to 0,2500 on M2 Board Dimensions
0,0 to 2750,0 on M2 Board Dimensions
